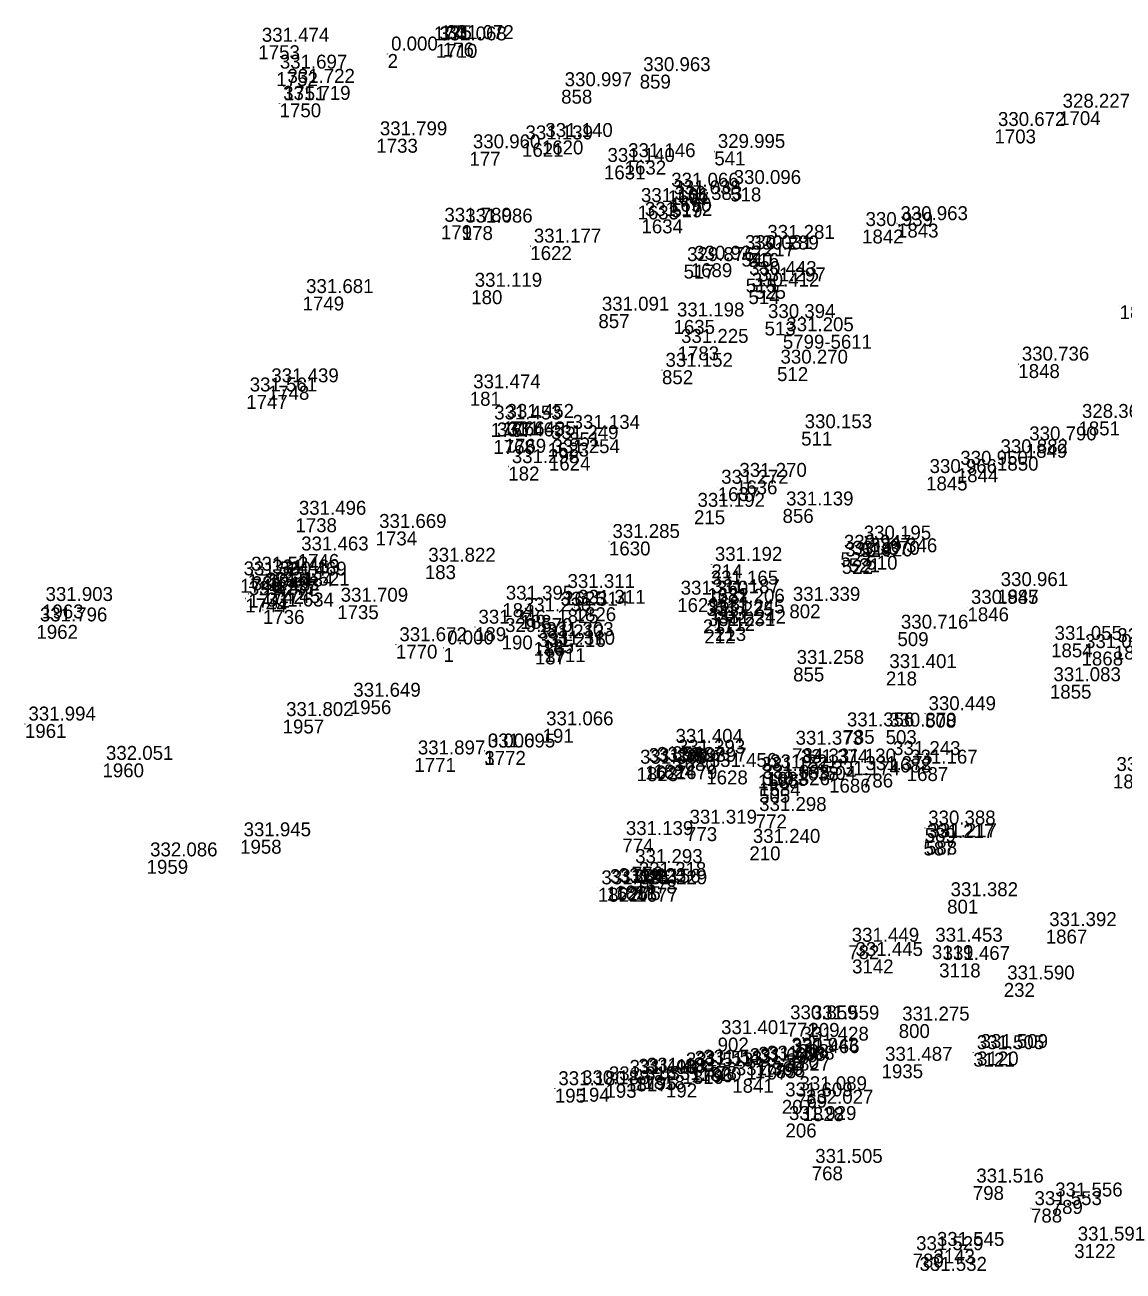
# Model space of a CAD drawing. Extents: x -829398 to -819400, y -1074439 to -1067977.
# Drawn here: x -819874 to -819779.5, y -1072361.1 to -1072253.8 of the extents above; entities that cross this region are included whole.
import ezdxf

# ---------------------------------------------------------------- set-up
doc = ezdxf.new("R2010")
doc.units = 0
for name, color, linetype in [('Vrstva 60', 7, 'Continuous'), ('Vrstva 61', 7, 'Continuous'), ('Čísla bodů_doměření_2012', 7, 'Continuous')]:
    doc.layers.add(name, color=color, linetype=linetype)

# ---------------------------------------------------------------- blocks, each defined once
blk = doc.blocks.new('BOD')
at = {"layer": 'Čísla bodů_doměření_2012'}
for p, q in [((-0.15, 0), (0.15, 0)), ((0, -0.15), (0, 0.15))]:
    blk.add_line(p, q, dxfattribs=at)

msp = doc.modelspace()

# ---------------------------------------------------------------- block references
at = {"layer": 'Vrstva 60', "xscale": 0.010000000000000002, "yscale": 0.010000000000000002}
for p in [(-819838.848, -1072253.935), (-819838.254, -1072253.831), (-819853.944, -1072255.554), (-819838.67, -1072255.433), (-819838.069, -1072255.322), (-819842.821, -1072256.307), (-819852.395, -1072257.865), (-819821.128, -1072258.081), (-819851.74, -1072259.089), (-819827.883, -1072259.38), (-819852.113, -1072260.553), (-819785.031, -1072261.227), (-819790.595, -1072262.803), (-819843.789, -1072263.603), (-819831.254, -1072263.956), (-819829.547, -1072263.748), (-819835.778, -1072264.723), (-819814.705, -1072264.694), (-819824.202, -1072265.898), (-819822.423, -1072265.485), (-819818.71, -1072268.029), (-819813.34, -1072267.795), (-819821.316, -1072269.346), (-819818.523, -1072268.681), (-819818.406, -1072269.166), (-819820.975, -1072270.541), (-819838.234, -1072271.045), (-819836.439, -1072271.115), (-819801.991, -1072271.413), (-819798.985, -1072270.905), (-819830.539, -1072272.838), (-819810.443, -1072272.52), (-819812.367, -1072273.399), (-819811.816, -1072273.435), (-819817.347, -1072274.43), (-819816.733, -1072274.312), (-819812.006, -1072275.631), (-819835.623, -1072276.639), (-819811.771, -1072276.627), (-819811.224, -1072276.18), (-819850.135, -1072277.181), (-819779.82, -1072277.925), (-819824.681, -1072278.696), (-819818.219, -1072279.197), (-819810.384, -1072279.331), (-819808.808, -1072280.471), (-819817.866, -1072281.47), (-819819.209, -1072283.527), (-819809.309, -1072283.257), (-819788.543, -1072282.995), (-819854.987, -1072285.648), (-819853.127, -1072284.863), (-819835.753, -1072285.38), (-819833.949, -1072288.061), (-819832.882, -1072287.928), (-819827.199, -1072288.87), (-819807.232, -1072288.813), (-819783.369, -1072287.929), (-819833.719, -1072289.52), (-819832.752, -1072289.426), (-819829.056, -1072289.755), (-819787.901, -1072289.859), (-819828.936, -1072290.958), (-819790.377, -1072290.967), (-819832.434, -1072291.818), (-819793.834, -1072291.962), (-819812.848, -1072293.001), (-819796.479, -1072292.669), (-819814.413, -1072293.589), (-819850.754, -1072296.263), (-819816.453, -1072295.579), (-819808.831, -1072295.46), (-819843.852, -1072297.396), (-819823.771, -1072298.261), (-819802.146, -1072298.394), (-819850.557, -1072299.337), (-819803.851, -1072299.19), (-819801.622, -1072299.488), (-819839.617, -1072300.303), (-819814.956, -1072300.229), (-819803.738, -1072299.846), (-819803.132, -1072299.708), (-819855.514, -1072301.476), (-819854.86, -1072301.075), (-819853.059, -1072301.316), (-819852.446, -1072301.498), (-819854.808, -1072302.756), (-819853.593, -1072302.436), (-819852.194, -1072302.363), (-819827.637, -1072302.565), (-819815.316, -1072302.271), (-819790.362, -1072302.401), (-819872.558, -1072303.683), (-819855.066, -1072303.164), (-819847.158, -1072303.745), (-819832.951, -1072303.569), (-819826.725, -1072303.923), (-819817.901, -1072303.137), (-819815.172, -1072303.018), (-819814.747, -1072303.831), (-819808.247, -1072303.673), (-819792.919, -1072303.932), (-819853.547, -1072304.159), (-819831.4, -1072304.585), (-819828.223, -1072304.091), (-819815.689, -1072304.972), (-819814.77, -1072304.752), (-819873.042, -1072305.44), (-819835.3, -1072305.636), (-819815.563, -1072305.836), (-819814.643, -1072305.622), (-819798.946, -1072306.065), (-819842.108, -1072307.143), (-819833.008, -1072306.352), (-819830.272, -1072306.901), (-819829.472, -1072306.699), (-819785.725, -1072307.032), (-819837.997, -1072307.425), (-819830.15, -1072307.638), (-819829.356, -1072307.444), (-819783.101, -1072307.737), (-819780.325, -1072307.222), (-819807.921, -1072309.103), (-819799.941, -1072309.456), (-819785.825, -1072310.588), (-819846.071, -1072311.921), (-819851.856, -1072313.585), (-819796.571, -1072313.08), (-819874.032, -1072313.971), (-819829.481, -1072314.385), (-819803.592, -1072314.476), (-819799.964, -1072314.498), (-819834.499, -1072316.291), (-819834.497, -1072316.291), (-819818.344, -1072315.891), (-819818.15, -1072316.812), (-819808.011, -1072316.051), (-819867.358, -1072317.358), (-819840.518, -1072316.889), (-819821.392, -1072317.687), (-819820.65, -1072317.545), (-819819.931, -1072317.451), (-819818.025, -1072317.52), (-819807.558, -1072317.639), (-819805.179, -1072317.581), (-819799.62, -1072316.941), (-819798.147, -1072317.679), (-819815.398, -1072317.966), (-819810.953, -1072318.305), (-819810.853, -1072318.974), (-819810.197, -1072318.092), (-819804.828, -1072318.678), (-819802, -1072318.233), (-819780.4, -1072318.315), (-819810.855, -1072319.542), (-819811.144, -1072321.758), (-819817.139, -1072322.849), (-819796.599, -1072322.92), (-819855.513, -1072323.934), (-819822.617, -1072323.827), (-819796.707, -1072324.081), (-819796.493, -1072324.012), (-819811.688, -1072324.503), (-819863.56, -1072325.662), (-819821.813, -1072326.238), (-819821.497, -1072327.355), (-819824.724, -1072328.07), (-819823.985, -1072327.964), (-819823.222, -1072327.878), (-819821.996, -1072327.927), (-819821.421, -1072328.067), (-819794.671, -1072329.091), (-819786.181, -1072331.665), (-819803.18, -1072333.011), (-819795.986, -1072333.007), (-819802.852, -1072334.235), (-819795.357, -1072334.579), (-819789.8, -1072336.256), (-819808.484, -1072339.685), (-819806.606, -1072339.7), (-819798.837, -1072339.794), (-819814.422, -1072340.96), (-819807.514, -1072341.522), (-819808.37, -1072342.474), (-819808.312, -1072342.597), (-819792.421, -1072342.258), (-819792.091, -1072342.154), (-819816.695, -1072343.603), (-819815.949, -1072343.499), (-819811.955, -1072343.374), (-819811.21, -1072343.254), (-819810.461, -1072343.159), (-819800.311, -1072343.258), (-819822.299, -1072344.385), (-819821.541, -1072344.288), (-819820.808, -1072344.191), (-819817.446, -1072343.741), (-819813.159, -1072344.504), (-819828.428, -1072345.356), (-819826.387, -1072345.278), (-819824.075, -1072344.936), (-819818.865, -1072344.907), (-819807.674, -1072345.792), (-819808.899, -1072346.32), (-819807.117, -1072346.951), (-819808.58, -1072348.352), (-819806.319, -1072352.043), (-819792.458, -1072353.734), (-819785.669, -1072354.932), (-819787.454, -1072355.677), (-819797.641, -1072359.553), (-819795.849, -1072359.19), (-819783.734, -1072358.731)]:
    msp.add_blockref('BOD', p, dxfattribs=at)

# ---------------------------------------------------------------- texts
at = {"layer": 'Vrstva 60'}
for s, p in [('174', (-819838.848, -1072255.135)), ('175', (-819838.254, -1072255.031)), ('1753', (-819853.944, -1072256.754)), ('1710', (-819838.67, -1072256.633)), ('176', (-819838.069, -1072256.522)), ('2', (-819842.821, -1072257.507)), ('1752', (-819852.395, -1072259.065)), ('859', (-819821.128, -1072259.281)), ('1751', (-819851.74, -1072260.289)), ('858', (-819827.883, -1072260.58)), ('1750', (-819852.113, -1072261.753)), ('1704', (-819785.031, -1072262.427)), ('1703', (-819790.595, -1072264.003)), ('1733', (-819843.789, -1072264.803)), ('1621', (-819831.254, -1072265.156)), ('1620', (-819829.547, -1072264.948)), ('177', (-819835.778, -1072265.923)), ('541', (-819814.705, -1072265.894)), ('1631', (-819824.202, -1072267.098)), ('1632', (-819822.423, -1072266.685)), ('1691', (-819818.71, -1072269.229)), ('518', (-819813.34, -1072268.995)), ('1633', (-819821.316, -1072270.546)), ('1690', (-819818.523, -1072269.881)), ('519', (-819818.406, -1072270.366)), ('1634', (-819820.975, -1072271.741)), ('179', (-819838.234, -1072272.245)), ('178', (-819836.439, -1072272.315)), ('1842', (-819801.991, -1072272.613)), ('1843', (-819798.985, -1072272.105)), ('1622', (-819830.539, -1072274.038)), ('217', (-819810.443, -1072273.72)), ('540', (-819812.367, -1072274.599)), ('516', (-819811.816, -1072274.635)), ('517', (-819817.347, -1072275.63)), ('1689', (-819816.733, -1072275.512)), ('515', (-819812.006, -1072276.831)), ('1749', (-819850.135, -1072278.381)), ('180', (-819835.623, -1072277.839)), ('514', (-819811.771, -1072277.827)), ('525', (-819811.224, -1072277.38)), ('1853', (-819779.82, -1072279.125)), ('857', (-819824.681, -1072279.896)), ('1635', (-819818.219, -1072280.397)), ('513', (-819810.384, -1072280.531)), ('1783', (-819817.866, -1072282.67)), ('5799-5611', (-819808.808, -1072281.671)), ('852', (-819819.209, -1072284.727)), ('512', (-819809.309, -1072284.457)), ('1848', (-819788.543, -1072284.195)), ('1747', (-819854.987, -1072286.848)), ('1748', (-819853.127, -1072286.063)), ('181', (-819835.753, -1072286.58)), ('1767', (-819833.949, -1072289.261)), ('1766', (-819832.882, -1072289.128)), ('851', (-819827.199, -1072290.07)), ('511', (-819807.232, -1072290.013)), ('1851', (-819783.369, -1072289.129)), ('1768', (-819833.719, -1072290.72)), ('1769', (-819832.752, -1072290.626)), ('1623', (-819829.056, -1072290.955)), ('1849', (-819787.901, -1072291.059)), ('1624', (-819828.936, -1072292.158)), ('1850', (-819790.377, -1072292.167)), ('182', (-819832.434, -1072293.018)), ('1844', (-819793.834, -1072293.162)), ('1636', (-819812.848, -1072294.201)), ('1845', (-819796.479, -1072293.869)), ('1637', (-819814.413, -1072294.789)), ('1738', (-819850.754, -1072297.463)), ('215', (-819816.453, -1072296.779)), ('856', (-819808.831, -1072296.66)), ('1734', (-819843.852, -1072298.596)), ('1630', (-819823.771, -1072299.461)), ('524', (-819802.146, -1072299.594)), ('1746', (-819850.557, -1072300.537)), ('523', (-819803.851, -1072300.39)), ('521', (-819803.132, -1072300.908)), ('510', (-819801.622, -1072300.688)), ('183', (-819839.617, -1072301.503)), ('214', (-819814.956, -1072301.429)), ('522', (-819803.738, -1072301.046)), ('1740', (-819855.514, -1072302.676)), ('1739', (-819854.86, -1072302.275)), ('1743', (-819853.059, -1072302.516)), ('1737', (-819852.446, -1072302.698)), ('1741', (-819854.808, -1072303.956)), ('1742', (-819853.593, -1072303.636)), ('1745', (-819852.194, -1072303.563)), ('1625', (-819827.637, -1072303.765)), ('1682', (-819815.316, -1072303.471)), ('1847', (-819790.362, -1072303.601)), ('1963', (-819872.558, -1072304.883)), ('1744', (-819855.066, -1072304.364)), ('1735', (-819847.158, -1072304.945)), ('184', (-819832.951, -1072304.769)), ('1826', (-819826.725, -1072305.123)), ('1629', (-819817.901, -1072304.337)), ('1681', (-819815.172, -1072304.218)), ('853', (-819814.747, -1072305.031)), ('802', (-819808.247, -1072304.873)), ('1846', (-819792.919, -1072305.132)), ('1736', (-819853.547, -1072305.359)), ('188', (-819831.4, -1072305.785)), ('1825', (-819828.223, -1072305.291)), ('211', (-819815.689, -1072306.172)), ('1712', (-819814.77, -1072305.952)), ('1962', (-819873.042, -1072306.64)), ('189', (-819835.3, -1072306.836)), ('212', (-819815.563, -1072307.036)), ('213', (-819814.643, -1072306.822)), ('509', (-819798.946, -1072307.265)), ('1770', (-819842.108, -1072308.343)), ('190', (-819833.008, -1072307.552)), ('186', (-819830.272, -1072308.101)), ('185', (-819829.472, -1072307.899)), ('1854', (-819785.725, -1072308.232)), ('1870', (-819780.325, -1072308.422)), ('1', (-819837.997, -1072308.625)), ('187', (-819830.15, -1072308.838)), ('1711', (-819829.356, -1072308.644)), ('1868', (-819783.101, -1072308.937)), ('855', (-819807.921, -1072310.303)), ('218', (-819799.941, -1072310.656)), ('1855', (-819785.825, -1072311.788)), ('1956', (-819846.071, -1072313.121)), ('1957', (-819851.856, -1072314.785)), ('508', (-819796.571, -1072314.28)), ('1961', (-819874.032, -1072315.171)), ('191', (-819829.481, -1072315.585)), ('785', (-819803.592, -1072315.676)), ('503', (-819799.964, -1072315.698)), ('3', (-819834.497, -1072317.491)), ('1772', (-819834.499, -1072317.491)), ('854', (-819818.344, -1072317.091)), ('1680', (-819818.15, -1072318.012)), ('784', (-819808.011, -1072317.251)), ('1960', (-819867.358, -1072318.558)), ('1771', (-819840.518, -1072318.089)), ('1823', (-819821.392, -1072318.887)), ('1627', (-819820.65, -1072318.745)), ('1824', (-819819.931, -1072318.651)), ('1679', (-819818.025, -1072318.72)), ('1638', (-819807.558, -1072318.839)), ('504', (-819805.179, -1072318.781)), ('1688', (-819799.62, -1072318.141)), ('1687', (-819798.147, -1072318.879)), ('1628', (-819815.398, -1072319.166)), ('1685', (-819810.953, -1072319.505)), ('1684', (-819810.853, -1072320.174)), ('1683', (-819810.197, -1072319.292)), ('1686', (-819804.828, -1072319.878)), ('786', (-819802, -1072319.433)), ('1856', (-819780.4, -1072319.515)), ('505', (-819810.855, -1072320.742)), ('772', (-819811.144, -1072322.958)), ('773', (-819817.139, -1072324.049)), ('589', (-819796.599, -1072324.12)), ('1958', (-819855.513, -1072325.134)), ('774', (-819822.617, -1072325.027)), ('587', (-819796.707, -1072325.281)), ('588', (-819796.493, -1072325.212)), ('210', (-819811.688, -1072325.703)), ('1959', (-819863.56, -1072326.862)), ('776', (-819821.813, -1072327.438)), ('1678', (-819821.497, -1072328.555)), ('1822', (-819824.724, -1072329.27)), ('1626', (-819823.985, -1072329.164)), ('1821', (-819823.222, -1072329.078)), ('775', (-819821.996, -1072329.127)), ('1677', (-819821.421, -1072329.267)), ('801', (-819794.671, -1072330.291)), ('1867', (-819786.181, -1072332.865)), ('782', (-819803.18, -1072334.211)), ('3119', (-819795.986, -1072334.207)), ('3142', (-819802.852, -1072335.435)), ('3118', (-819795.357, -1072335.779)), ('232', (-819789.8, -1072337.456)), ('771', (-819808.484, -1072340.885)), ('209', (-819806.606, -1072340.9)), ('800', (-819798.837, -1072340.994)), ('902', (-819814.422, -1072342.16)), ('208', (-819807.514, -1072342.722)), ('770', (-819808.37, -1072343.674)), ('1827', (-819808.312, -1072343.797)), ('3121', (-819792.421, -1072343.458)), ('3120', (-819792.091, -1072343.354)), ('1796', (-819816.695, -1072344.803)), ('1820', (-819815.949, -1072344.699)), ('1797', (-819811.955, -1072344.574)), ('1785', (-819811.21, -1072344.454)), ('1798', (-819810.461, -1072344.359)), ('1935', (-819800.311, -1072344.458)), ('1817', (-819822.299, -1072345.585)), ('1795', (-819821.541, -1072345.488)), ('1818', (-819820.808, -1072345.391)), ('1819', (-819817.446, -1072344.941)), ('1841', (-819813.159, -1072345.704)), ('195', (-819828.428, -1072346.556)), ('194', (-819826.387, -1072346.478)), ('193', (-819824.075, -1072346.136)), ('192', (-819818.865, -1072346.107)), ('769', (-819807.674, -1072346.992)), ('207', (-819808.899, -1072347.52)), ('1828', (-819807.117, -1072348.151)), ('206', (-819808.58, -1072349.552)), ('768', (-819806.319, -1072353.243)), ('798', (-819792.458, -1072354.934)), ('789', (-819785.669, -1072356.132)), ('788', (-819787.454, -1072356.877)), ('780', (-819797.641, -1072360.753)), ('3143', (-819795.849, -1072360.39)), ('3122', (-819783.734, -1072359.931))]:
    msp.add_text(s, height=1.2, dxfattribs=at).set_placement(p)
at = {"layer": 'Vrstva 61'}
for s, p in [('331.474', (-819853.644, -1072255.254)), ('331.068', (-819838.37, -1072255.133)), ('331.072', (-819837.769, -1072255.022)), ('0.000', (-819842.521, -1072256.007)), ('331.697', (-819852.095, -1072257.565)), ('330.963', (-819820.828, -1072257.781)), ('331.722', (-819851.44, -1072258.789)), ('330.997', (-819827.583, -1072259.08)), ('331.719', (-819851.813, -1072260.253)), ('328.227', (-819784.731, -1072260.927)), ('331.799', (-819843.489, -1072263.303)), ('330.672', (-819790.295, -1072262.503)), ('330.960', (-819835.478, -1072264.423)), ('331.139', (-819830.954, -1072263.656)), ('331.140', (-819829.247, -1072263.448)), ('329.995', (-819814.405, -1072264.394)), ('331.146', (-819822.123, -1072265.185)), ('331.140', (-819823.902, -1072265.598)), ('330.096', (-819813.04, -1072267.495)), ('331.066', (-819818.41, -1072267.729)), ('331.038', (-819818.223, -1072268.381)), ('331.166', (-819821.016, -1072269.046)), ('330.383', (-819818.106, -1072268.866)), ('331.789', (-819837.934, -1072270.745)), ('331.086', (-819836.139, -1072270.815)), ('331.172', (-819820.675, -1072270.241)), ('330.963', (-819798.685, -1072270.605)), ('330.939', (-819801.691, -1072271.113)), ('331.177', (-819830.239, -1072272.538)), ('331.281', (-819810.143, -1072272.22)), ('330.922', (-819816.433, -1072274.012)), ('330.031', (-819812.067, -1072273.099)), ('330.289', (-819811.516, -1072273.135)), ('329.876', (-819817.047, -1072274.13)), ('330.443', (-819811.706, -1072275.331)), ('331.297', (-819810.924, -1072275.88)), ('331.681', (-819849.835, -1072276.881)), ('331.119', (-819835.323, -1072276.339)), ('330.412', (-819811.471, -1072276.327)), ('331.091', (-819824.381, -1072278.396)), ('331.198', (-819817.919, -1072278.897)), ('330.394', (-819810.084, -1072279.031)), ('331.205', (-819808.508, -1072280.171)), ('331.225', (-819817.566, -1072281.17)), ('331.152', (-819818.909, -1072283.227)), ('330.270', (-819809.009, -1072282.957)), ('330.736', (-819788.243, -1072282.695)), ('331.439', (-819852.827, -1072284.563)), ('331.561', (-819854.687, -1072285.348)), ('331.474', (-819835.453, -1072285.08)), ('331.453', (-819833.649, -1072287.761)), ('331.452', (-819832.582, -1072287.628)), ('328.366', (-819783.069, -1072287.629)), ('331.134', (-819826.899, -1072288.57)), ('330.153', (-819806.932, -1072288.513)), ('331.465', (-819833.419, -1072289.22)), ('331.435', (-819832.452, -1072289.126)), ('331.249', (-819828.756, -1072289.455)), ('330.790', (-819787.601, -1072289.559)), ('331.254', (-819828.636, -1072290.658)), ('330.882', (-819790.077, -1072290.667)), ('331.298', (-819832.134, -1072291.518)), ('330.950', (-819793.534, -1072291.662)), ('331.272', (-819814.113, -1072293.289)), ('331.270', (-819812.548, -1072292.701)), ('330.966', (-819796.179, -1072292.369)), ('331.192', (-819816.153, -1072295.279)), ('331.139', (-819808.531, -1072295.16)), ('331.496', (-819850.454, -1072295.963)), ('331.669', (-819843.552, -1072297.096)), ('331.285', (-819823.471, -1072297.961)), ('330.195', (-819801.846, -1072298.094)), ('331.463', (-819850.257, -1072299.037)), ('330.947', (-819803.551, -1072298.89)), ('330.920', (-819803.438, -1072299.546)), ('331.370', (-819802.832, -1072299.408)), ('330.346', (-819801.322, -1072299.188)), ('331.524', (-819854.56, -1072300.775)), ('331.822', (-819839.317, -1072300.003)), ('331.192', (-819814.656, -1072299.929)), ('331.560', (-819855.214, -1072301.176)), ('331.463', (-819852.759, -1072301.016)), ('331.469', (-819852.146, -1072301.198)), ('331.165', (-819815.016, -1072301.971)), ('331.277', (-819854.766, -1072302.864)), ('331.493', (-819854.508, -1072302.456)), ('331.484', (-819853.293, -1072302.136)), ('331.521', (-819851.894, -1072302.063)), ('331.311', (-819827.337, -1072302.265)), ('331.360', (-819817.601, -1072302.837)), ('331.187', (-819814.872, -1072302.718)), ('330.961', (-819790.062, -1072302.101)), ('331.903', (-819872.258, -1072303.383)), ('331.634', (-819853.247, -1072303.859)), ('331.709', (-819846.858, -1072303.445)), ('331.395', (-819832.651, -1072303.269)), ('331.314', (-819827.923, -1072303.791)), ('331.311', (-819826.425, -1072303.623)), ('331.206', (-819814.447, -1072303.531)), ('331.339', (-819807.947, -1072303.373)), ('330.985', (-819792.619, -1072303.632)), ('331.796', (-819872.742, -1072305.14)), ('331.230', (-819831.1, -1072304.285)), ('331.225', (-819815.389, -1072304.672)), ('331.245', (-819814.47, -1072304.452)), ('331.246', (-819835, -1072305.336)), ('329.570', (-819832.708, -1072306.052)), ('331.231', (-819815.263, -1072305.536)), ('331.242', (-819814.343, -1072305.322)), ('330.716', (-819798.646, -1072305.765)), ('331.672', (-819841.808, -1072306.843)), ('0.000', (-819837.697, -1072307.125)), ('331.213', (-819829.972, -1072306.601)), ('331.216', (-819829.85, -1072307.338)), ('331.303', (-819829.172, -1072306.399)), ('331.310', (-819829.056, -1072307.144)), ('331.055', (-819785.425, -1072306.732)), ('329.413', (-819780.025, -1072306.922)), ('331.099', (-819782.801, -1072307.437)), ('331.258', (-819807.621, -1072308.803)), ('331.401', (-819799.641, -1072309.156)), ('331.083', (-819785.525, -1072310.288)), ('331.649', (-819845.771, -1072311.621)), ('331.994', (-819873.732, -1072313.671)), ('331.802', (-819851.556, -1072313.285)), ('330.449', (-819796.271, -1072312.78)), ('331.066', (-819829.181, -1072314.085)), ('331.356', (-819803.292, -1072314.176)), ('330.870', (-819799.664, -1072314.198)), ('331.404', (-819818.044, -1072315.591)), ('331.373', (-819807.711, -1072315.751)), ('331.897', (-819840.218, -1072316.589)), ('331.695', (-819834.199, -1072315.991)), ('0.000', (-819834.197, -1072315.991)), ('331.393', (-819817.85, -1072316.512)), ('331.243', (-819799.32, -1072316.641)), ('332.051', (-819867.058, -1072317.058)), ('331.369', (-819821.092, -1072317.387)), ('331.369', (-819820.35, -1072317.245)), ('331.387', (-819819.631, -1072317.151)), ('331.397', (-819817.725, -1072317.22)), ('331.456', (-819815.098, -1072317.666)), ('331.157', (-819810.653, -1072318.005)), ('331.221', (-819809.897, -1072317.792)), ('331.374', (-819807.258, -1072317.339)), ('331.130', (-819804.879, -1072317.281)), ('331.372', (-819801.7, -1072317.933)), ('331.167', (-819797.847, -1072317.379)), ('331.243', (-819780.1, -1072318.015)), ('331.095', (-819810.553, -1072318.674)), ('331.174', (-819804.528, -1072318.378)), ('330.826', (-819810.555, -1072319.242)), ('331.298', (-819810.844, -1072321.458)), ('331.319', (-819816.839, -1072322.549)), ('330.388', (-819796.299, -1072322.62)), ('331.945', (-819855.213, -1072323.634)), ('331.139', (-819822.317, -1072323.527)), ('331.240', (-819811.388, -1072324.203)), ('331.217', (-819796.407, -1072323.781)), ('331.217', (-819796.193, -1072323.712)), ('332.086', (-819863.26, -1072325.362)), ('331.293', (-819821.513, -1072325.938)), ('331.423', (-819823.685, -1072327.664)), ('331.423', (-819822.922, -1072327.578)), ('331.156', (-819821.696, -1072327.627)), ('331.218', (-819821.197, -1072327.055)), ('331.425', (-819824.424, -1072327.77)), ('331.229', (-819821.121, -1072327.767)), ('331.382', (-819794.371, -1072328.791)), ('331.392', (-819785.881, -1072331.365)), ('331.449', (-819802.88, -1072332.711)), ('331.453', (-819795.686, -1072332.707)), ('331.445', (-819802.552, -1072333.935)), ('331.467', (-819795.057, -1072334.279)), ('331.590', (-819789.5, -1072335.956)), ('330.859', (-819808.184, -1072339.385)), ('331.559', (-819806.306, -1072339.4)), ('331.275', (-819798.537, -1072339.494)), ('331.401', (-819814.122, -1072340.66)), ('331.428', (-819807.214, -1072341.222)), ('330.943', (-819808.07, -1072342.174)), ('331.466', (-819808.012, -1072342.297)), ('331.505', (-819792.121, -1072341.958)), ('331.509', (-819791.791, -1072341.854)), ('331.513', (-819817.146, -1072343.441)), ('331.513', (-819816.395, -1072343.303)), ('331.543', (-819815.649, -1072343.199)), ('331.608', (-819811.655, -1072343.074)), ('331.608', (-819810.91, -1072342.954)), ('331.608', (-819810.161, -1072342.859)), ('331.487', (-819800.011, -1072342.958)), ('331.316', (-819823.775, -1072344.636)), ('331.490', (-819821.999, -1072344.085)), ('331.488', (-819821.241, -1072343.988)), ('331.488', (-819820.508, -1072343.891)), ('331.478', (-819818.565, -1072344.607)), ('331.365', (-819812.859, -1072344.204)), ('331.180', (-819828.128, -1072345.056)), ('330.188', (-819826.087, -1072344.978)), ('331.089', (-819807.374, -1072345.492)), ('331.609', (-819808.599, -1072346.02)), ('332.027', (-819806.817, -1072346.651)), ('331.929', (-819808.28, -1072348.052)), ('331.505', (-819806.019, -1072351.743)), ('331.516', (-819792.158, -1072353.434)), ('331.553', (-819787.154, -1072355.377)), ('331.556', (-819785.369, -1072354.632)), ('331.591', (-819783.434, -1072358.431)), ('331.529', (-819797.341, -1072359.253)), ('331.545', (-819795.549, -1072358.89)), ('331.532', (-819797.047, -1072361.037))]:
    msp.add_text(s, height=1.2, dxfattribs=at).set_placement(p)

doc.saveas('drawing.dxf')
